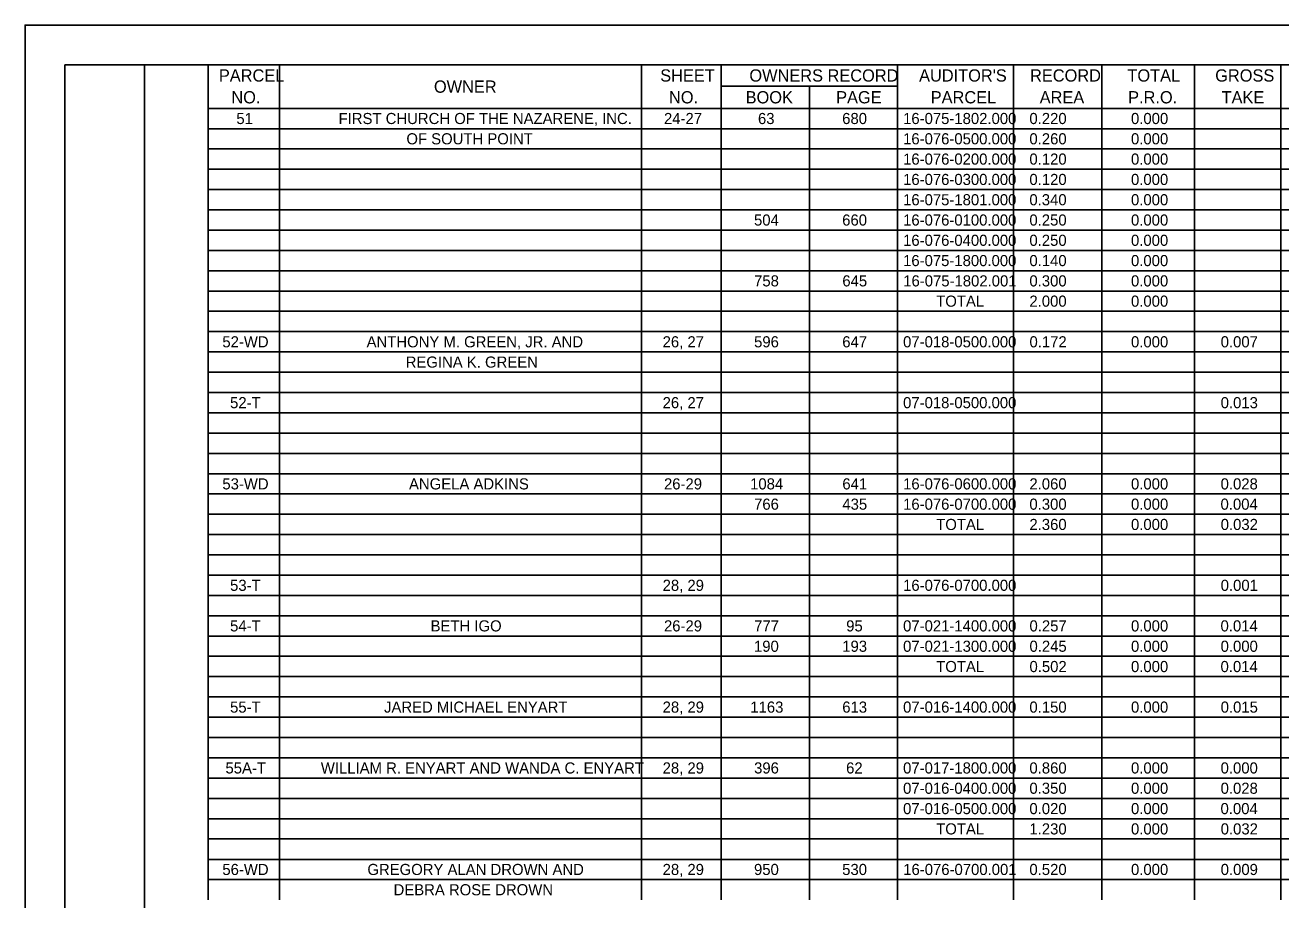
# Model space of a CAD drawing. Extents: x 0 to 52.9, y -1.2 to 22.
# Drawn here: x 0 to 15.78, y 11 to 22 of the extents above; entities that cross this region are included whole.
import ezdxf

# ---------------------------------------------------------------- set-up
doc = ezdxf.new("R2010")
doc.units = 0
for name, color, linetype in [('Default', 7, 'Continuous'), ('SH_Border', 7, 'Continuous'), ('SH_Cut_Line', 7, 'Continuous')]:
    doc.layers.add(name, color=color, linetype=linetype)

msp = doc.modelspace()

# ---------------------------------------------------------------- linework, layer by layer
at = {"layer": 'Default'}
for p, q in [((2.298, 21.5), (12.418, 21.5)), ((2.298, 21.5), (2.298, 21.233)), ((3.195, 21.5), (3.195, 21.233)), ((7.743, 21.5), (7.743, 21.233)), ((8.745, 21.5), (8.745, 21.233)), ((10.961, 21.5), (10.961, 21.233)), ((12.418, 21.5), (13.246, 21.5)), ((12.418, 21.5), (12.418, 21.233)), ((13.246, 21.5), (13.526, 21.5)), ((13.526, 21.5), (15.776, 21.5)), ((13.526, 21.5), (13.526, 21.233)), ((14.692, 21.5), (14.692, 21.233)), ((15.776, 21.5), (27.996, 21.5)), ((15.776, 21.5), (15.776, 21.233)), ((2.298, 21.233), (2.298, 20.698)), ((3.195, 21.233), (3.195, 20.698)), ((7.743, 21.233), (7.743, 20.698)), ((8.745, 21.233), (10.961, 21.233)), ((8.745, 21.233), (8.745, 20.698)), ((9.853, 21.233), (9.853, 20.698)), ((10.961, 21.233), (10.961, 20.698)), ((12.418, 21.233), (12.418, 20.698)), ((13.526, 21.233), (13.526, 20.698)), ((14.692, 21.233), (14.692, 20.698)), ((15.776, 21.233), (15.776, 20.698)), ((2.298, 20.953), (12.418, 20.953)), ((12.418, 20.953), (13.246, 20.953)), ((13.246, 20.953), (13.526, 20.953)), ((13.526, 20.953), (15.776, 20.953)), ((15.776, 20.953), (27.996, 20.953)), ((2.298, 20.698), (12.418, 20.698)), ((2.298, 20.698), (2.298, 19.933)), ((3.195, 20.698), (3.195, 19.933)), ((7.743, 20.698), (7.743, 19.933)), ((8.745, 20.698), (8.745, 19.933)), ((9.853, 20.698), (9.853, 19.933)), ((10.961, 20.698), (10.961, 19.933)), ((12.418, 20.698), (13.246, 20.698)), ((12.418, 20.698), (12.418, 19.933)), ((13.246, 20.698), (13.526, 20.698)), ((13.526, 20.698), (15.776, 20.698)), ((13.526, 20.698), (13.526, 19.933)), ((14.692, 20.698), (14.692, 19.933)), ((15.776, 20.698), (27.996, 20.698)), ((15.776, 20.698), (15.776, 19.933)), ((2.298, 20.443), (12.418, 20.443)), ((12.418, 20.443), (13.246, 20.443)), ((13.246, 20.443), (13.526, 20.443)), ((13.526, 20.443), (15.776, 20.443)), ((15.776, 20.443), (27.996, 20.443)), ((2.298, 20.188), (12.418, 20.188)), ((12.418, 20.188), (13.246, 20.188)), ((13.246, 20.188), (13.526, 20.188)), ((13.526, 20.188), (15.776, 20.188)), ((15.776, 20.188), (27.996, 20.188)), ((2.298, 19.933), (12.418, 19.933)), ((2.298, 19.933), (2.298, 19.167)), ((3.195, 19.933), (3.195, 19.167)), ((7.743, 19.933), (7.743, 19.167)), ((8.745, 19.933), (8.745, 19.167)), ((9.853, 19.933), (9.853, 19.167)), ((10.961, 19.933), (10.961, 19.167)), ((12.418, 19.933), (13.246, 19.933)), ((12.418, 19.933), (12.418, 19.167)), ((13.246, 19.933), (13.526, 19.933)), ((13.526, 19.933), (15.776, 19.933)), ((13.526, 19.933), (13.526, 19.167)), ((14.692, 19.933), (14.692, 19.167)), ((15.776, 19.933), (27.996, 19.933)), ((15.776, 19.933), (15.776, 19.167)), ((2.298, 19.678), (12.418, 19.678)), ((12.418, 19.678), (13.246, 19.678)), ((13.246, 19.678), (13.526, 19.678)), ((13.526, 19.678), (15.776, 19.678)), ((15.776, 19.678), (27.996, 19.678)), ((2.298, 19.422), (12.418, 19.422)), ((12.418, 19.422), (13.246, 19.422)), ((13.246, 19.422), (13.526, 19.422)), ((13.526, 19.422), (15.776, 19.422)), ((15.776, 19.422), (27.996, 19.422)), ((2.298, 19.167), (12.418, 19.167)), ((2.298, 19.167), (2.298, 18.912)), ((3.195, 19.167), (3.195, 18.912)), ((7.743, 19.167), (7.743, 18.912)), ((8.745, 19.167), (8.745, 18.912)), ((9.853, 19.167), (9.853, 18.912)), ((10.961, 19.167), (10.961, 18.912)), ((12.418, 19.167), (13.246, 19.167)), ((12.418, 19.167), (12.418, 18.912)), ((13.246, 19.167), (13.526, 19.167)), ((13.526, 19.167), (15.776, 19.167)), ((13.526, 19.167), (13.526, 18.912)), ((14.692, 19.167), (14.692, 18.912)), ((15.776, 19.167), (27.996, 19.167)), ((15.776, 19.167), (15.776, 18.912)), ((2.298, 18.912), (12.418, 18.912)), ((2.298, 18.912), (2.298, 18.657)), ((3.195, 18.912), (3.195, 18.657)), ((7.743, 18.912), (7.743, 18.657)), ((8.745, 18.912), (8.745, 18.657)), ((9.853, 18.912), (9.853, 18.657)), ((10.961, 18.912), (10.961, 18.657)), ((12.418, 18.912), (13.246, 18.912)), ((12.418, 18.912), (12.418, 18.657)), ((13.246, 18.912), (13.526, 18.912)), ((13.526, 18.912), (15.776, 18.912)), ((13.526, 18.912), (13.526, 18.657)), ((14.692, 18.912), (14.692, 18.657)), ((15.776, 18.912), (27.996, 18.912)), ((15.776, 18.912), (15.776, 18.657)), ((2.298, 18.657), (10.961, 18.657)), ((2.298, 18.657), (2.298, 17.381)), ((3.195, 18.657), (3.195, 17.381)), ((7.743, 18.657), (7.743, 17.381)), ((8.745, 18.657), (8.745, 17.381)), ((9.853, 18.657), (9.853, 17.381)), ((10.961, 18.657), (12.418, 18.657)), ((10.961, 18.657), (10.961, 17.381)), ((12.418, 18.657), (13.246, 18.657)), ((12.418, 18.657), (12.418, 17.381)), ((13.246, 18.657), (13.526, 18.657)), ((13.526, 18.657), (14.692, 18.657)), ((13.526, 18.657), (13.526, 17.381)), ((14.692, 18.657), (15.776, 18.657)), ((14.692, 18.657), (14.692, 17.381)), ((15.776, 18.657), (27.996, 18.657)), ((15.776, 18.657), (15.776, 17.381)), ((2.298, 18.402), (12.418, 18.402)), ((12.418, 18.402), (13.246, 18.402)), ((13.246, 18.402), (13.526, 18.402)), ((13.526, 18.402), (15.776, 18.402)), ((15.776, 18.402), (27.996, 18.402)), ((2.298, 18.147), (12.418, 18.147)), ((12.418, 18.147), (13.246, 18.147)), ((13.246, 18.147), (13.526, 18.147)), ((13.526, 18.147), (15.776, 18.147)), ((15.776, 18.147), (27.996, 18.147)), ((2.298, 17.892), (12.418, 17.892)), ((12.418, 17.892), (13.246, 17.892)), ((13.246, 17.892), (13.526, 17.892)), ((13.526, 17.892), (15.776, 17.892)), ((15.776, 17.892), (27.996, 17.892)), ((2.298, 17.637), (12.418, 17.637)), ((12.418, 17.637), (13.246, 17.637)), ((13.246, 17.637), (13.526, 17.637)), ((13.526, 17.637), (15.776, 17.637)), ((15.776, 17.637), (27.996, 17.637)), ((2.298, 17.381), (12.418, 17.381)), ((2.298, 17.381), (2.298, 17.126)), ((3.195, 17.381), (3.195, 17.126)), ((7.743, 17.381), (7.743, 17.126)), ((8.745, 17.381), (8.745, 17.126)), ((9.853, 17.381), (9.853, 17.126)), ((10.961, 17.381), (10.961, 17.126)), ((12.418, 17.381), (13.246, 17.381)), ((12.418, 17.381), (12.418, 17.126)), ((13.246, 17.381), (13.526, 17.381)), ((13.526, 17.381), (15.776, 17.381)), ((13.526, 17.381), (13.526, 17.126)), ((14.692, 17.381), (14.692, 17.126)), ((15.776, 17.381), (27.996, 17.381)), ((15.776, 17.381), (15.776, 17.126)), ((2.298, 17.126), (12.418, 17.126)), ((2.298, 17.126), (2.298, 16.871)), ((3.195, 17.126), (3.195, 16.871)), ((7.743, 17.126), (7.743, 16.871)), ((8.745, 17.126), (8.745, 16.871)), ((9.853, 17.126), (9.853, 16.871)), ((10.961, 17.126), (10.961, 16.871)), ((12.418, 17.126), (13.246, 17.126)), ((12.418, 17.126), (12.418, 16.871)), ((13.246, 17.126), (13.526, 17.126)), ((13.526, 17.126), (15.776, 17.126)), ((13.526, 17.126), (13.526, 16.871)), ((14.692, 17.126), (14.692, 16.871)), ((15.776, 17.126), (27.996, 17.126)), ((15.776, 17.126), (15.776, 16.871)), ((2.298, 16.871), (12.418, 16.871)), ((2.298, 16.871), (2.298, 16.616)), ((3.195, 16.871), (3.195, 16.616)), ((7.743, 16.871), (7.743, 16.616)), ((8.745, 16.871), (8.745, 16.616)), ((9.853, 16.871), (9.853, 16.616)), ((10.961, 16.871), (10.961, 16.616)), ((12.418, 16.871), (13.246, 16.871)), ((12.418, 16.871), (12.418, 16.616)), ((13.246, 16.871), (13.526, 16.871)), ((13.526, 16.871), (15.776, 16.871)), ((13.526, 16.871), (13.526, 16.616)), ((14.692, 16.871), (14.692, 16.616)), ((15.776, 16.871), (27.996, 16.871)), ((15.776, 16.871), (15.776, 16.616)), ((2.298, 16.616), (12.418, 16.616)), ((2.298, 16.616), (2.298, 16.106)), ((3.195, 16.616), (3.195, 16.106)), ((7.743, 16.616), (7.743, 16.106)), ((8.745, 16.616), (8.745, 16.106)), ((9.853, 16.616), (9.853, 16.106)), ((10.961, 16.616), (10.961, 16.106)), ((12.418, 16.616), (13.246, 16.616)), ((12.418, 16.616), (12.418, 16.106)), ((13.246, 16.616), (13.526, 16.616)), ((13.526, 16.616), (15.776, 16.616)), ((13.526, 16.616), (13.526, 16.106)), ((14.692, 16.616), (14.692, 16.106)), ((15.776, 16.616), (27.996, 16.616)), ((15.776, 16.616), (15.776, 16.106)), ((2.298, 16.361), (12.418, 16.361)), ((12.418, 16.361), (13.246, 16.361)), ((13.246, 16.361), (13.526, 16.361)), ((13.526, 16.361), (15.776, 16.361)), ((15.776, 16.361), (27.996, 16.361)), ((2.298, 16.106), (12.418, 16.106)), ((2.298, 16.106), (2.298, 15.851)), ((3.195, 16.106), (3.195, 15.851)), ((7.743, 16.106), (7.743, 15.851)), ((8.745, 16.106), (8.745, 15.851)), ((9.853, 16.106), (9.853, 15.851)), ((10.961, 16.106), (10.961, 15.851)), ((12.418, 16.106), (13.246, 16.106)), ((12.418, 16.106), (12.418, 15.851)), ((13.246, 16.106), (13.526, 16.106)), ((13.526, 16.106), (15.776, 16.106)), ((13.526, 16.106), (13.526, 15.851)), ((14.692, 16.106), (14.692, 15.851)), ((15.776, 16.106), (27.996, 16.106)), ((15.776, 16.106), (15.776, 15.851)), ((2.298, 15.851), (10.961, 15.851)), ((2.298, 15.851), (2.298, 15.596)), ((3.195, 15.851), (3.195, 15.596)), ((7.743, 15.851), (7.743, 15.596)), ((8.745, 15.851), (8.745, 15.596)), ((9.853, 15.851), (9.853, 15.596)), ((10.961, 15.851), (12.418, 15.851)), ((10.961, 15.851), (10.961, 15.596)), ((12.418, 15.851), (13.246, 15.851)), ((12.418, 15.851), (12.418, 15.596)), ((13.246, 15.851), (13.526, 15.851)), ((13.526, 15.851), (15.776, 15.851)), ((13.526, 15.851), (13.526, 15.596)), ((14.692, 15.851), (14.692, 15.596)), ((15.776, 15.851), (17.945, 15.851)), ((15.776, 15.851), (15.776, 15.596)), ((2.298, 15.596), (12.418, 15.596)), ((2.298, 15.596), (2.298, 15.34)), ((3.195, 15.596), (3.195, 15.34)), ((7.743, 15.596), (7.743, 15.34)), ((8.745, 15.596), (8.745, 15.34)), ((9.853, 15.596), (9.853, 15.34)), ((10.961, 15.596), (10.961, 15.34)), ((12.418, 15.596), (13.246, 15.596)), ((12.418, 15.596), (12.418, 15.34)), ((13.246, 15.596), (13.526, 15.596)), ((13.526, 15.596), (15.776, 15.596)), ((13.526, 15.596), (13.526, 15.34)), ((14.692, 15.596), (14.692, 15.34)), ((15.776, 15.596), (27.996, 15.596)), ((15.776, 15.596), (15.776, 15.34)), ((2.298, 15.34), (12.418, 15.34)), ((2.298, 15.34), (2.298, 14.83)), ((3.195, 15.34), (3.195, 14.83)), ((7.743, 15.34), (7.743, 14.83)), ((8.745, 15.34), (8.745, 14.83)), ((9.853, 15.34), (9.853, 14.83)), ((10.961, 15.34), (10.961, 14.83)), ((12.418, 15.34), (13.246, 15.34)), ((12.418, 15.34), (12.418, 14.83)), ((13.246, 15.34), (13.526, 15.34)), ((13.526, 15.34), (15.776, 15.34)), ((13.526, 15.34), (13.526, 14.83)), ((14.692, 15.34), (14.692, 14.83)), ((15.776, 15.34), (27.996, 15.34)), ((15.776, 15.34), (15.776, 14.83)), ((2.298, 15.085), (12.418, 15.085)), ((12.418, 15.085), (13.246, 15.085)), ((13.246, 15.085), (13.526, 15.085)), ((13.526, 15.085), (15.776, 15.085)), ((15.776, 15.085), (27.996, 15.085)), ((2.298, 14.83), (12.418, 14.83)), ((2.298, 14.83), (2.298, 14.575)), ((3.195, 14.83), (3.195, 14.575)), ((7.743, 14.83), (7.743, 14.575)), ((8.745, 14.83), (8.745, 14.575)), ((9.853, 14.83), (9.853, 14.575)), ((10.961, 14.83), (10.961, 14.575)), ((12.418, 14.83), (13.246, 14.83)), ((12.418, 14.83), (12.418, 14.575)), ((13.246, 14.83), (13.526, 14.83)), ((13.526, 14.83), (15.776, 14.83)), ((13.526, 14.83), (13.526, 14.575)), ((14.692, 14.83), (14.692, 14.575)), ((15.776, 14.83), (27.996, 14.83)), ((15.776, 14.83), (15.776, 14.575)), ((2.298, 14.575), (12.418, 14.575)), ((2.298, 14.575), (2.298, 11.513)), ((3.195, 14.575), (3.195, 11.513)), ((7.743, 14.575), (7.743, 11.513)), ((8.745, 14.575), (8.745, 11.513)), ((9.853, 14.575), (9.853, 11.513)), ((10.961, 14.575), (10.961, 11.513)), ((12.418, 14.575), (13.246, 14.575)), ((12.418, 14.575), (12.418, 11.513)), ((13.246, 14.575), (13.526, 14.575)), ((13.526, 14.575), (15.776, 14.575)), ((13.526, 14.575), (13.526, 11.513)), ((14.692, 14.575), (14.692, 11.513)), ((15.776, 14.575), (27.996, 14.575)), ((15.776, 14.575), (15.776, 11.513)), ((2.298, 14.32), (12.418, 14.32)), ((12.418, 14.32), (13.246, 14.32)), ((13.246, 14.32), (13.526, 14.32)), ((13.526, 14.32), (15.776, 14.32)), ((15.776, 14.32), (27.996, 14.32)), ((2.298, 14.065), (10.961, 14.065)), ((10.961, 14.065), (12.418, 14.065)), ((12.418, 14.065), (13.246, 14.065)), ((13.246, 14.065), (13.526, 14.065)), ((13.526, 14.065), (15.776, 14.065)), ((15.776, 14.065), (17.945, 14.065)), ((2.298, 13.81), (12.418, 13.81)), ((12.418, 13.81), (13.246, 13.81)), ((13.246, 13.81), (13.526, 13.81)), ((13.526, 13.81), (15.776, 13.81)), ((15.776, 13.81), (27.996, 13.81)), ((2.298, 13.554), (12.418, 13.554)), ((12.418, 13.554), (13.246, 13.554)), ((13.246, 13.554), (13.526, 13.554)), ((13.526, 13.554), (15.776, 13.554)), ((15.776, 13.554), (27.996, 13.554)), ((2.298, 13.299), (12.418, 13.299)), ((12.418, 13.299), (13.246, 13.299)), ((13.246, 13.299), (13.526, 13.299)), ((13.526, 13.299), (15.776, 13.299)), ((15.776, 13.299), (27.996, 13.299)), ((2.298, 13.044), (12.418, 13.044)), ((12.418, 13.044), (13.246, 13.044)), ((13.246, 13.044), (13.526, 13.044)), ((13.526, 13.044), (15.776, 13.044)), ((15.776, 13.044), (27.996, 13.044)), ((2.298, 12.789), (12.418, 12.789)), ((12.418, 12.789), (13.246, 12.789)), ((13.246, 12.789), (13.526, 12.789)), ((13.526, 12.789), (15.776, 12.789)), ((15.776, 12.789), (27.996, 12.789)), ((2.298, 12.534), (12.418, 12.534)), ((12.418, 12.534), (13.246, 12.534)), ((13.246, 12.534), (13.526, 12.534)), ((13.526, 12.534), (15.776, 12.534)), ((15.776, 12.534), (27.996, 12.534)), ((2.298, 12.279), (12.418, 12.279)), ((12.418, 12.279), (13.246, 12.279)), ((13.246, 12.279), (13.526, 12.279)), ((13.526, 12.279), (15.776, 12.279)), ((15.776, 12.279), (27.996, 12.279)), ((2.298, 12.024), (10.961, 12.024)), ((10.961, 12.024), (12.418, 12.024)), ((12.418, 12.024), (13.246, 12.024)), ((13.246, 12.024), (13.526, 12.024)), ((13.526, 12.024), (15.776, 12.024)), ((15.776, 12.024), (17.945, 12.024)), ((2.298, 11.769), (12.418, 11.769)), ((12.418, 11.769), (13.246, 11.769)), ((13.246, 11.769), (13.526, 11.769)), ((13.526, 11.769), (15.776, 11.769)), ((15.776, 11.769), (27.996, 11.769)), ((2.298, 11.513), (12.418, 11.513)), ((2.298, 11.513), (2.298, 11.258)), ((3.195, 11.513), (3.195, 11.258)), ((7.743, 11.513), (7.743, 11.258)), ((8.745, 11.513), (8.745, 11.258)), ((9.853, 11.513), (9.853, 11.258)), ((10.961, 11.513), (10.961, 11.258)), ((12.418, 11.513), (13.246, 11.513)), ((12.418, 11.513), (12.418, 11.258)), ((13.246, 11.513), (13.526, 11.513)), ((13.526, 11.513), (15.776, 11.513)), ((13.526, 11.513), (13.526, 11.258)), ((14.692, 11.513), (14.692, 11.258)), ((15.776, 11.513), (27.996, 11.513)), ((15.776, 11.513), (15.776, 11.258)), ((2.298, 11.258), (12.418, 11.258)), ((2.298, 11.258), (2.298, 11.003)), ((3.195, 11.258), (3.195, 11.003)), ((7.743, 11.258), (7.743, 11.003)), ((8.745, 11.258), (8.745, 11.003)), ((9.853, 11.258), (9.853, 11.003)), ((10.961, 11.258), (10.961, 11.003)), ((12.418, 11.258), (13.246, 11.258)), ((12.418, 11.258), (12.418, 11.003)), ((13.246, 11.258), (13.526, 11.258)), ((13.526, 11.258), (15.776, 11.258)), ((13.526, 11.258), (13.526, 11.003)), ((14.692, 11.258), (14.692, 11.003)), ((15.776, 11.258), (27.996, 11.258)), ((15.776, 11.258), (15.776, 11.003))]:
    msp.add_line(p, q, dxfattribs=at)
at = {"layer": 'SH_Border'}
for points in [[(0.5, 21.5), (1.5, 21.5), (1.5, 0.5), (0.5, 0.5)], [(1.5, 21.5), (33.5, 21.5), (33.5, 0.5), (1.5, 0.5)]]:
    msp.add_lwpolyline(points, close=True, dxfattribs=at)
at = {"layer": 'SH_Cut_Line'}
msp.add_lwpolyline([(0, 0), (34, 0), (34, 22), (0, 22)], close=True, dxfattribs=at)

# ---------------------------------------------------------------- texts
at = {"layer": 'Default'}
for s, height, p in [('PARCEL', 0.1537, (2.434, 21.29)), ('OWNER', 0.1537, (5.136, 21.15)), ('SHEET', 0.1537, (7.979, 21.29)), ('OWNERS RECORD', 0.15369, (9.099, 21.29)), ("AUDITOR'S", 0.1537, (11.231, 21.29)), ('RECORD', 0.1537, (12.625, 21.29)), ('TOTAL', 0.1537, (13.848, 21.29)), ('GROSS', 0.1537, (14.951, 21.29)), ('NO.', 0.1537, (2.591, 21.016)), ('NO.', 0.1537, (8.089, 21.016)), ('BOOK', 0.1537, (9.052, 21.016)), ('PAGE', 0.1537, (10.189, 21.016)), ('PARCEL', 0.1537, (11.377, 21.016)), ('AREA', 0.1537, (12.746, 21.016)), ('P.R.O.', 0.1537, (13.857, 21.016)), ('TAKE', 0.1537, (15.031, 21.016)), ('51', 0.1397, (2.654, 20.756)), ('FIRST CHURCH OF THE NAZARENE, INC.', 0.13971, (3.938, 20.756)), ('24-27', 0.1397, (8.026, 20.756)), ('63', 0.1397, (9.207, 20.756)), ('680', 0.1397, (10.265, 20.756)), ('16-075-1802.000', 0.13971, (11.03, 20.756)), ('0.220', 0.1397, (12.617, 20.756)), ('0.000', 0.1397, (13.893, 20.756)), ('OF SOUTH POINT', 0.13971, (4.79, 20.501)), ('16-076-0500.000', 0.13971, (11.03, 20.501)), ('0.260', 0.1397, (12.617, 20.501)), ('0.000', 0.1397, (13.893, 20.501)), ('16-076-0200.000', 0.13971, (11.03, 20.246)), ('0.120', 0.1397, (12.617, 20.246)), ('0.000', 0.1397, (13.893, 20.246)), ('16-076-0300.000', 0.13971, (11.03, 19.99)), ('0.120', 0.1397, (12.617, 19.99)), ('0.000', 0.1397, (13.893, 19.99)), ('16-075-1801.000', 0.13971, (11.03, 19.735)), ('0.340', 0.1397, (12.617, 19.735)), ('0.000', 0.1397, (13.893, 19.735)), ('504', 0.1397, (9.157, 19.48)), ('660', 0.1397, (10.265, 19.48)), ('16-076-0100.000', 0.13971, (11.03, 19.48)), ('0.250', 0.1397, (12.617, 19.48)), ('0.000', 0.1397, (13.893, 19.48)), ('16-076-0400.000', 0.13971, (11.03, 19.225)), ('0.250', 0.1397, (12.617, 19.225)), ('0.000', 0.1397, (13.893, 19.225)), ('16-075-1800.000', 0.13971, (11.03, 18.97)), ('0.140', 0.1397, (12.617, 18.97)), ('0.000', 0.1397, (13.893, 18.97)), ('758', 0.1397, (9.158, 18.715)), ('645', 0.1397, (10.267, 18.715)), ('16-075-1802.001', 0.13971, (11.032, 18.715)), ('0.300', 0.1397, (12.617, 18.715)), ('0.000', 0.1397, (13.893, 18.715)), ('TOTAL', 0.1397, (11.446, 18.46)), ('2.000', 0.1397, (12.617, 18.46)), ('0.000', 0.1397, (13.893, 18.46)), ('52-WD', 0.1397, (2.478, 17.949)), ('ANTHONY M. GREEN, JR. AND', 0.13971, (4.29, 17.949)), ('26, 27', 0.1397, (8.009, 17.949)), ('596', 0.1397, (9.158, 17.949)), ('647', 0.1397, (10.266, 17.949)), ('07-018-0500.000', 0.13971, (11.03, 17.949)), ('0.172', 0.1397, (12.618, 17.949)), ('0.000', 0.1397, (13.893, 17.949)), ('0.007', 0.1397, (15.02, 17.949)), ('REGINA K. GREEN', 0.13971, (4.781, 17.694)), ('52-T', 0.1397, (2.575, 17.184)), ('26, 27', 0.1397, (8.009, 17.184)), ('07-018-0500.000', 0.13971, (11.03, 17.184)), ('0.013', 0.1397, (15.02, 17.184)), ('53-WD', 0.1397, (2.478, 16.163)), ('ANGELA ADKINS', 0.13971, (4.823, 16.163)), ('26-29', 0.1397, (8.026, 16.163)), ('1084', 0.1397, (9.108, 16.163)), ('641', 0.1397, (10.267, 16.163)), ('16-076-0600.000', 0.13971, (11.03, 16.163)), ('2.060', 0.1397, (12.617, 16.163)), ('0.000', 0.1397, (13.893, 16.163)), ('0.028', 0.1397, (15.019, 16.163)), ('766', 0.1397, (9.158, 15.908)), ('435', 0.1397, (10.267, 15.908)), ('16-076-0700.000', 0.13971, (11.03, 15.908)), ('0.300', 0.1397, (12.617, 15.908)), ('0.000', 0.1397, (13.893, 15.908)), ('0.004', 0.1397, (15.018, 15.908)), ('TOTAL', 0.1397, (11.446, 15.653)), ('2.360', 0.1397, (12.617, 15.653)), ('0.000', 0.1397, (13.893, 15.653)), ('0.032', 0.1397, (15.02, 15.653)), ('53-T', 0.1397, (2.575, 14.888)), ('28, 29', 0.1397, (8.009, 14.888)), ('16-076-0700.000', 0.13971, (11.03, 14.888)), ('0.001', 0.1397, (15.02, 14.888)), ('54-T', 0.1397, (2.575, 14.378)), ('BETH IGO', 0.1397, (5.094, 14.378)), ('26-29', 0.1397, (8.026, 14.378)), ('777', 0.1397, (9.159, 14.378)), ('95', 0.1397, (10.315, 14.378)), ('07-021-1400.000', 0.13971, (11.03, 14.378)), ('0.257', 0.1397, (12.618, 14.378)), ('0.000', 0.1397, (13.893, 14.378)), ('0.014', 0.1397, (15.018, 14.378)), ('190', 0.1397, (9.157, 14.122)), ('193', 0.1397, (10.266, 14.122)), ('07-021-1300.000', 0.13971, (11.03, 14.122)), ('0.245', 0.1397, (12.618, 14.122)), ('0.000', 0.1397, (13.893, 14.122)), ('0.000', 0.1397, (15.019, 14.122)), ('TOTAL', 0.1397, (11.446, 13.867)), ('0.502', 0.1397, (12.618, 13.867)), ('0.000', 0.1397, (13.893, 13.867)), ('0.014', 0.1397, (15.018, 13.867)), ('55-T', 0.1397, (2.575, 13.357)), ('JARED MICHAEL ENYART', 0.13971, (4.509, 13.357)), ('28, 29', 0.1397, (8.009, 13.357)), ('1163', 0.1397, (9.111, 13.357)), ('613', 0.1397, (10.266, 13.357)), ('07-016-1400.000', 0.13971, (11.03, 13.357)), ('0.150', 0.1397, (12.617, 13.357)), ('0.000', 0.1397, (13.893, 13.357)), ('0.015', 0.1397, (15.02, 13.357)), ('55A-T', 0.1397, (2.517, 12.592)), ('WILLIAM R. ENYART AND WANDA C. ENYART', 0.13971, (3.715, 12.592)), ('28, 29', 0.1397, (8.009, 12.592)), ('396', 0.1397, (9.158, 12.592)), ('62', 0.1397, (10.314, 12.592)), ('07-017-1800.000', 0.13971, (11.03, 12.592)), ('0.860', 0.1397, (12.617, 12.592)), ('0.000', 0.1397, (13.893, 12.592)), ('0.000', 0.1397, (15.019, 12.592)), ('07-016-0400.000', 0.13971, (11.03, 12.337)), ('0.350', 0.1397, (12.617, 12.337)), ('0.000', 0.1397, (13.893, 12.337)), ('0.028', 0.1397, (15.019, 12.337)), ('07-016-0500.000', 0.13971, (11.03, 12.081)), ('0.020', 0.1397, (12.617, 12.081)), ('0.000', 0.1397, (13.893, 12.081)), ('0.004', 0.1397, (15.018, 12.081)), ('TOTAL', 0.1397, (11.446, 11.826)), ('1.230', 0.1397, (12.617, 11.826)), ('0.000', 0.1397, (13.893, 11.826)), ('0.032', 0.1397, (15.02, 11.826)), ('56-WD', 0.1397, (2.478, 11.316)), ('GREGORY ALAN DROWN AND', 0.13971, (4.3, 11.316)), ('28, 29', 0.1397, (8.009, 11.316)), ('950', 0.1397, (9.157, 11.316)), ('530', 0.1397, (10.265, 11.316)), ('16-076-0700.001', 0.13971, (11.032, 11.316)), ('0.520', 0.1397, (12.617, 11.316)), ('0.000', 0.1397, (13.893, 11.316)), ('0.009', 0.1397, (15.02, 11.316)), ('DEBRA ROSE DROWN', 0.13971, (4.629, 11.061))]:
    msp.add_text(s, height=height, dxfattribs=at).set_placement(p)

doc.saveas('drawing.dxf')
